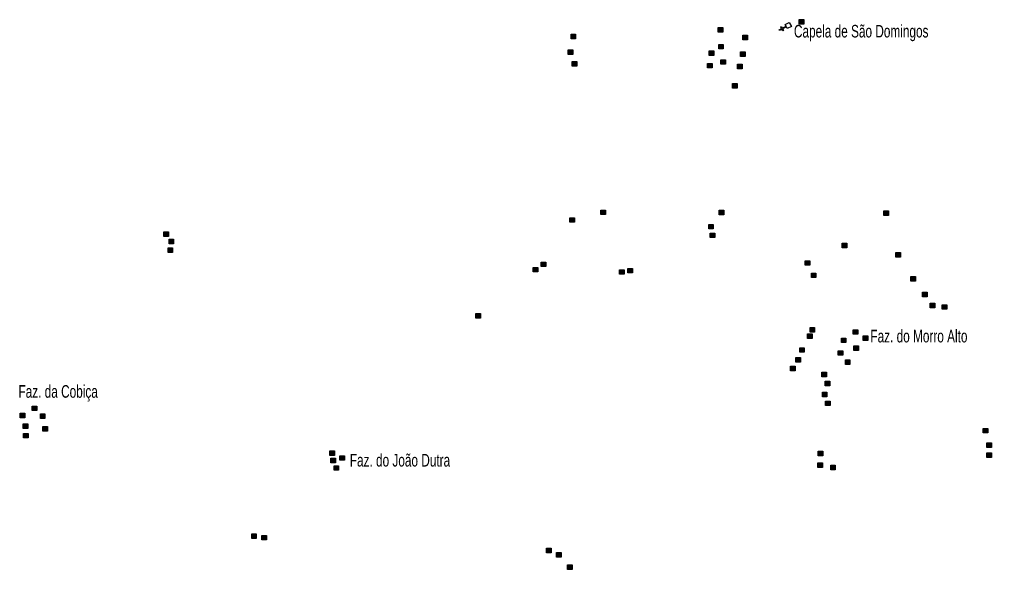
# Model space of a CAD drawing. Extents: x 265.7 to 292.1, y 7676.2 to 7704.2.
# Drawn here: x 273.19 to 279.36, y 7679.7 to 7683.19 of the extents above; entities that cross this region are included whole.
import ezdxf

# ---------------------------------------------------------------- set-up
doc = ezdxf.new("R2010")
doc.units = 0
doc.header["$LTSCALE"] = 0.032
doc.layers.add('2', color=7, linetype='Continuous', lineweight=25)
doc.layers.add('6', color=7, linetype='Continuous', lineweight=25)
doc.layers.add('61', color=7, linetype='Continuous')

msp = doc.modelspace()

# ---------------------------------------------------------------- hatches: boundary and pattern name
at = {"layer": '2'}
for points in [[(278.1366, 7683.192), (278.1656, 7683.192), (278.1656, 7683.163), (278.1366, 7683.163)], [(277.6228, 7683.1404), (277.6518, 7683.1404), (277.6518, 7683.1114), (277.6228, 7683.1114)], [(276.6889, 7683.0976), (276.7179, 7683.0976), (276.7179, 7683.0686), (276.6889, 7683.0686)], [(277.7786, 7683.0921), (277.8076, 7683.0921), (277.8076, 7683.0631), (277.7786, 7683.0631)], [(277.6259, 7683.0339), (277.6549, 7683.0339), (277.6549, 7683.0049), (277.6259, 7683.0049)], [(276.6712, 7682.9983), (276.7002, 7682.9983), (276.7002, 7682.9693), (276.6712, 7682.9693)], [(277.5647, 7682.9919), (277.5937, 7682.9919), (277.5937, 7682.9629), (277.5647, 7682.9629)], [(277.7649, 7682.9854), (277.7939, 7682.9854), (277.7939, 7682.9564), (277.7649, 7682.9564)], [(276.6955, 7682.925), (276.7245, 7682.925), (276.7245, 7682.896), (276.6955, 7682.896)], [(277.5549, 7682.9129), (277.5839, 7682.9129), (277.5839, 7682.8839), (277.5549, 7682.8839)], [(277.6397, 7682.9363), (277.6687, 7682.9363), (277.6687, 7682.9073), (277.6397, 7682.9073)], [(277.7455, 7682.9071), (277.7745, 7682.9071), (277.7745, 7682.8781), (277.7455, 7682.8781)], [(277.7139, 7682.7845), (277.7429, 7682.7845), (277.7429, 7682.7555), (277.7139, 7682.7555)], [(276.8787, 7681.9823), (276.9077, 7681.9823), (276.9077, 7681.9533), (276.8787, 7681.9533)], [(277.6284, 7681.9816), (277.6574, 7681.9816), (277.6574, 7681.9526), (277.6284, 7681.9526)], [(278.6744, 7681.9766), (278.7034, 7681.9766), (278.7034, 7681.9476), (278.6744, 7681.9476)], [(276.6817, 7681.9331), (276.7107, 7681.9331), (276.7107, 7681.9041), (276.6817, 7681.9041)], [(274.1056, 7681.8427), (274.1346, 7681.8427), (274.1346, 7681.8137), (274.1056, 7681.8137)], [(277.5622, 7681.8911), (277.5912, 7681.8911), (277.5912, 7681.8621), (277.5622, 7681.8621)], [(277.5719, 7681.8362), (277.6009, 7681.8362), (277.6009, 7681.8072), (277.5719, 7681.8072)], [(274.1379, 7681.7966), (274.1669, 7681.7966), (274.1669, 7681.7676), (274.1379, 7681.7676)], [(278.4088, 7681.7709), (278.4378, 7681.7709), (278.4378, 7681.7419), (278.4088, 7681.7419)], [(274.1314, 7681.7425), (274.1604, 7681.7425), (274.1604, 7681.7135), (274.1314, 7681.7135)], [(278.7502, 7681.712), (278.7792, 7681.712), (278.7792, 7681.683), (278.7502, 7681.683)], [(276.4993, 7681.6521), (276.5283, 7681.6521), (276.5283, 7681.6231), (276.4993, 7681.6231)], [(278.1739, 7681.6603), (278.2029, 7681.6603), (278.2029, 7681.6313), (278.1739, 7681.6313)], [(276.4493, 7681.6183), (276.4783, 7681.6183), (276.4783, 7681.5893), (276.4493, 7681.5893)], [(276.9964, 7681.603), (277.0254, 7681.603), (277.0254, 7681.574), (276.9964, 7681.574)], [(277.0498, 7681.6119), (277.0788, 7681.6119), (277.0788, 7681.5829), (277.0498, 7681.5829)], [(278.2136, 7681.5821), (278.2426, 7681.5821), (278.2426, 7681.5531), (278.2136, 7681.5531)], [(278.8454, 7681.5601), (278.8744, 7681.5601), (278.8744, 7681.5311), (278.8454, 7681.5311)], [(278.9197, 7681.4601), (278.9487, 7681.4601), (278.9487, 7681.4311), (278.9197, 7681.4311)], [(278.9681, 7681.39), (278.9971, 7681.39), (278.9971, 7681.361), (278.9681, 7681.361)], [(279.0439, 7681.381), (279.0729, 7681.381), (279.0729, 7681.352), (279.0439, 7681.352)], [(276.0846, 7681.3245), (276.1136, 7681.3245), (276.1136, 7681.2955), (276.0846, 7681.2955)], [(278.2054, 7681.2359), (278.2344, 7681.2359), (278.2344, 7681.2069), (278.2054, 7681.2069)], [(278.479, 7681.2221), (278.508, 7681.2221), (278.508, 7681.1931), (278.479, 7681.1931)], [(278.1892, 7681.1954), (278.2182, 7681.1954), (278.2182, 7681.1664), (278.1892, 7681.1664)], [(278.404, 7681.1696), (278.433, 7681.1696), (278.433, 7681.1406), (278.404, 7681.1406)], [(278.5428, 7681.1827), (278.5718, 7681.1827), (278.5718, 7681.1537), (278.5428, 7681.1537)], [(278.14, 7681.1082), (278.169, 7681.1082), (278.169, 7681.0792), (278.14, 7681.0792)], [(278.4831, 7681.1204), (278.5121, 7681.1204), (278.5121, 7681.0914), (278.4831, 7681.0914)], [(278.115, 7681.0461), (278.144, 7681.0461), (278.144, 7681.0171), (278.115, 7681.0171)], [(278.3845, 7681.0889), (278.4135, 7681.0889), (278.4135, 7681.0599), (278.3845, 7681.0599)], [(278.4297, 7681.0308), (278.4587, 7681.0308), (278.4587, 7681.0018), (278.4297, 7681.0018)], [(278.0812, 7680.9904), (278.1102, 7680.9904), (278.1102, 7680.9614), (278.0812, 7680.9614)], [(278.2798, 7680.9533), (278.3088, 7680.9533), (278.3088, 7680.9243), (278.2798, 7680.9243)], [(278.3022, 7680.8952), (278.3312, 7680.8952), (278.3312, 7680.8662), (278.3022, 7680.8662)], [(278.2838, 7680.8259), (278.3128, 7680.8259), (278.3128, 7680.7969), (278.2838, 7680.7969)], [(273.2695, 7680.7378), (273.2985, 7680.7378), (273.2985, 7680.7088), (273.2695, 7680.7088)], [(278.3031, 7680.7693), (278.3321, 7680.7693), (278.3321, 7680.7403), (278.3031, 7680.7403)], [(273.1928, 7680.6926), (273.2218, 7680.6926), (273.2218, 7680.6636), (273.1928, 7680.6636)], [(273.3212, 7680.6878), (273.3502, 7680.6878), (273.3502, 7680.6588), (273.3212, 7680.6588)], [(273.213, 7680.624), (273.242, 7680.624), (273.242, 7680.595), (273.213, 7680.595)], [(273.3373, 7680.6071), (273.3663, 7680.6071), (273.3663, 7680.5781), (273.3373, 7680.5781)], [(273.2147, 7680.5642), (273.2437, 7680.5642), (273.2437, 7680.5352), (273.2147, 7680.5352)], [(279.3038, 7680.5958), (279.3328, 7680.5958), (279.3328, 7680.5668), (279.3038, 7680.5668)], [(279.3273, 7680.5047), (279.3563, 7680.5047), (279.3563, 7680.4757), (279.3273, 7680.4757)], [(275.1587, 7680.4529), (275.1877, 7680.4529), (275.1877, 7680.4239), (275.1587, 7680.4239)], [(275.2218, 7680.4223), (275.2508, 7680.4223), (275.2508, 7680.3933), (275.2218, 7680.3933)], [(278.2572, 7680.4505), (278.2862, 7680.4505), (278.2862, 7680.4215), (278.2572, 7680.4215)], [(279.3281, 7680.4401), (279.3571, 7680.4401), (279.3571, 7680.4111), (279.3281, 7680.4111)], [(275.1653, 7680.4061), (275.1943, 7680.4061), (275.1943, 7680.3771), (275.1653, 7680.3771)], [(275.1846, 7680.3593), (275.2136, 7680.3593), (275.2136, 7680.3303), (275.1846, 7680.3303)], [(278.2555, 7680.377), (278.2845, 7680.377), (278.2845, 7680.348), (278.2555, 7680.348)], [(278.3362, 7680.3625), (278.3652, 7680.3625), (278.3652, 7680.3335), (278.3362, 7680.3335)], [(274.6625, 7679.9267), (274.6915, 7679.9267), (274.6915, 7679.8977), (274.6625, 7679.8977)], [(274.7271, 7679.917), (274.7561, 7679.917), (274.7561, 7679.888), (274.7271, 7679.888)], [(276.5332, 7679.8354), (276.5622, 7679.8354), (276.5622, 7679.8064), (276.5332, 7679.8064)], [(276.597, 7679.8073), (276.626, 7679.8073), (276.626, 7679.7783), (276.597, 7679.7783)], [(276.6672, 7679.7289), (276.6962, 7679.7289), (276.6962, 7679.6999), (276.6672, 7679.6999)]]:
    msp.add_hatch(color=256, dxfattribs=at).paths.add_polyline_path(points)

# ---------------------------------------------------------------- linework, layer by layer
for points in [[(278.1366, 7683.192), (278.1656, 7683.192), (278.1656, 7683.163), (278.1366, 7683.163)], [(277.6228, 7683.1404), (277.6518, 7683.1404), (277.6518, 7683.1114), (277.6228, 7683.1114)], [(276.6889, 7683.0976), (276.7179, 7683.0976), (276.7179, 7683.0686), (276.6889, 7683.0686)], [(277.7786, 7683.0921), (277.8076, 7683.0921), (277.8076, 7683.0631), (277.7786, 7683.0631)], [(277.6259, 7683.0339), (277.6549, 7683.0339), (277.6549, 7683.0049), (277.6259, 7683.0049)], [(276.6712, 7682.9983), (276.7002, 7682.9983), (276.7002, 7682.9693), (276.6712, 7682.9693)], [(277.5647, 7682.9919), (277.5937, 7682.9919), (277.5937, 7682.9629), (277.5647, 7682.9629)], [(277.7649, 7682.9854), (277.7939, 7682.9854), (277.7939, 7682.9564), (277.7649, 7682.9564)], [(276.6955, 7682.925), (276.7245, 7682.925), (276.7245, 7682.896), (276.6955, 7682.896)], [(277.5549, 7682.9129), (277.5839, 7682.9129), (277.5839, 7682.8839), (277.5549, 7682.8839)], [(277.6397, 7682.9363), (277.6687, 7682.9363), (277.6687, 7682.9073), (277.6397, 7682.9073)], [(277.7455, 7682.9071), (277.7745, 7682.9071), (277.7745, 7682.8781), (277.7455, 7682.8781)], [(277.7139, 7682.7845), (277.7429, 7682.7845), (277.7429, 7682.7555), (277.7139, 7682.7555)], [(276.8787, 7681.9823), (276.9077, 7681.9823), (276.9077, 7681.9533), (276.8787, 7681.9533)], [(277.6284, 7681.9816), (277.6574, 7681.9816), (277.6574, 7681.9526), (277.6284, 7681.9526)], [(278.6744, 7681.9766), (278.7034, 7681.9766), (278.7034, 7681.9476), (278.6744, 7681.9476)], [(276.6817, 7681.9331), (276.7107, 7681.9331), (276.7107, 7681.9041), (276.6817, 7681.9041)], [(274.1056, 7681.8427), (274.1346, 7681.8427), (274.1346, 7681.8137), (274.1056, 7681.8137)], [(277.5622, 7681.8911), (277.5912, 7681.8911), (277.5912, 7681.8621), (277.5622, 7681.8621)], [(277.5719, 7681.8362), (277.6009, 7681.8362), (277.6009, 7681.8072), (277.5719, 7681.8072)], [(274.1379, 7681.7966), (274.1669, 7681.7966), (274.1669, 7681.7676), (274.1379, 7681.7676)], [(278.4088, 7681.7709), (278.4378, 7681.7709), (278.4378, 7681.7419), (278.4088, 7681.7419)], [(274.1314, 7681.7425), (274.1604, 7681.7425), (274.1604, 7681.7135), (274.1314, 7681.7135)], [(278.7502, 7681.712), (278.7792, 7681.712), (278.7792, 7681.683), (278.7502, 7681.683)], [(276.4993, 7681.6521), (276.5283, 7681.6521), (276.5283, 7681.6231), (276.4993, 7681.6231)], [(278.1739, 7681.6603), (278.2029, 7681.6603), (278.2029, 7681.6313), (278.1739, 7681.6313)], [(276.4493, 7681.6183), (276.4783, 7681.6183), (276.4783, 7681.5893), (276.4493, 7681.5893)], [(276.9964, 7681.603), (277.0254, 7681.603), (277.0254, 7681.574), (276.9964, 7681.574)], [(277.0498, 7681.6119), (277.0788, 7681.6119), (277.0788, 7681.5829), (277.0498, 7681.5829)], [(278.2136, 7681.5821), (278.2426, 7681.5821), (278.2426, 7681.5531), (278.2136, 7681.5531)], [(278.8454, 7681.5601), (278.8744, 7681.5601), (278.8744, 7681.5311), (278.8454, 7681.5311)], [(278.9197, 7681.4601), (278.9487, 7681.4601), (278.9487, 7681.4311), (278.9197, 7681.4311)], [(278.9681, 7681.39), (278.9971, 7681.39), (278.9971, 7681.361), (278.9681, 7681.361)], [(279.0439, 7681.381), (279.0729, 7681.381), (279.0729, 7681.352), (279.0439, 7681.352)], [(276.0846, 7681.3245), (276.1136, 7681.3245), (276.1136, 7681.2955), (276.0846, 7681.2955)], [(278.2054, 7681.2359), (278.2344, 7681.2359), (278.2344, 7681.2069), (278.2054, 7681.2069)], [(278.479, 7681.2221), (278.508, 7681.2221), (278.508, 7681.1931), (278.479, 7681.1931)], [(278.1892, 7681.1954), (278.2182, 7681.1954), (278.2182, 7681.1664), (278.1892, 7681.1664)], [(278.404, 7681.1696), (278.433, 7681.1696), (278.433, 7681.1406), (278.404, 7681.1406)], [(278.5428, 7681.1827), (278.5718, 7681.1827), (278.5718, 7681.1537), (278.5428, 7681.1537)], [(278.14, 7681.1082), (278.169, 7681.1082), (278.169, 7681.0792), (278.14, 7681.0792)], [(278.4831, 7681.1204), (278.5121, 7681.1204), (278.5121, 7681.0914), (278.4831, 7681.0914)], [(278.115, 7681.0461), (278.144, 7681.0461), (278.144, 7681.0171), (278.115, 7681.0171)], [(278.3845, 7681.0889), (278.4135, 7681.0889), (278.4135, 7681.0599), (278.3845, 7681.0599)], [(278.4297, 7681.0308), (278.4587, 7681.0308), (278.4587, 7681.0018), (278.4297, 7681.0018)], [(278.0812, 7680.9904), (278.1102, 7680.9904), (278.1102, 7680.9614), (278.0812, 7680.9614)], [(278.2798, 7680.9533), (278.3088, 7680.9533), (278.3088, 7680.9243), (278.2798, 7680.9243)], [(278.3022, 7680.8952), (278.3312, 7680.8952), (278.3312, 7680.8662), (278.3022, 7680.8662)], [(278.2838, 7680.8259), (278.3128, 7680.8259), (278.3128, 7680.7969), (278.2838, 7680.7969)], [(273.2695, 7680.7378), (273.2985, 7680.7378), (273.2985, 7680.7088), (273.2695, 7680.7088)], [(278.3031, 7680.7693), (278.3321, 7680.7693), (278.3321, 7680.7403), (278.3031, 7680.7403)], [(273.1928, 7680.6926), (273.2218, 7680.6926), (273.2218, 7680.6636), (273.1928, 7680.6636)], [(273.3212, 7680.6878), (273.3502, 7680.6878), (273.3502, 7680.6588), (273.3212, 7680.6588)], [(273.213, 7680.624), (273.242, 7680.624), (273.242, 7680.595), (273.213, 7680.595)], [(273.3373, 7680.6071), (273.3663, 7680.6071), (273.3663, 7680.5781), (273.3373, 7680.5781)], [(273.2147, 7680.5642), (273.2437, 7680.5642), (273.2437, 7680.5352), (273.2147, 7680.5352)], [(279.3038, 7680.5958), (279.3328, 7680.5958), (279.3328, 7680.5668), (279.3038, 7680.5668)], [(279.3273, 7680.5047), (279.3563, 7680.5047), (279.3563, 7680.4757), (279.3273, 7680.4757)], [(275.1587, 7680.4529), (275.1877, 7680.4529), (275.1877, 7680.4239), (275.1587, 7680.4239)], [(275.2218, 7680.4223), (275.2508, 7680.4223), (275.2508, 7680.3933), (275.2218, 7680.3933)], [(278.2572, 7680.4505), (278.2862, 7680.4505), (278.2862, 7680.4215), (278.2572, 7680.4215)], [(279.3281, 7680.4401), (279.3571, 7680.4401), (279.3571, 7680.4111), (279.3281, 7680.4111)], [(275.1653, 7680.4061), (275.1943, 7680.4061), (275.1943, 7680.3771), (275.1653, 7680.3771)], [(275.1846, 7680.3593), (275.2136, 7680.3593), (275.2136, 7680.3303), (275.1846, 7680.3303)], [(278.2555, 7680.377), (278.2845, 7680.377), (278.2845, 7680.348), (278.2555, 7680.348)], [(278.3362, 7680.3625), (278.3652, 7680.3625), (278.3652, 7680.3335), (278.3362, 7680.3335)], [(274.6625, 7679.9267), (274.6915, 7679.9267), (274.6915, 7679.8977), (274.6625, 7679.8977)], [(274.7271, 7679.917), (274.7561, 7679.917), (274.7561, 7679.888), (274.7271, 7679.888)], [(276.5332, 7679.8354), (276.5622, 7679.8354), (276.5622, 7679.8064), (276.5332, 7679.8064)], [(276.597, 7679.8073), (276.626, 7679.8073), (276.626, 7679.7783), (276.597, 7679.7783)], [(276.6672, 7679.7289), (276.6962, 7679.7289), (276.6962, 7679.6999), (276.6672, 7679.6999)]]:
    msp.add_lwpolyline(points, close=True, dxfattribs=at)
at = {"layer": '6'}
for points in [[(278.0553, 7683.1451), (278.0313, 7683.1326), (278.0369, 7683.1218), (278.0325, 7683.1196), (278.0269, 7683.1303), (278.0124, 7683.1227), (278.0102, 7683.1269), (278.0247, 7683.1345), (278.0191, 7683.1453), (278.0234, 7683.1475), (278.029, 7683.1368), (278.053, 7683.1494)], [(278.053, 7683.1494), (278.0474, 7683.1601), (278.0731, 7683.1736), (278.0866, 7683.1479), (278.0609, 7683.1344), (278.0553, 7683.1451)]]:
    msp.add_lwpolyline(points, dxfattribs=at)

# ---------------------------------------------------------------- texts
at = {"layer": '61', "width": 0.7}
for s, p in [('Capela de São Domingos', (278.1033, 7683.0774)), ('Faz. do Morro Alto', (278.5883, 7681.1418)), ('Faz. da Cobiça', (273.1822, 7680.7906)), ('Faz. do João Dutra', (275.2846, 7680.3538))]:
    msp.add_text(s, height=0.08, dxfattribs=at).set_placement(p)

doc.saveas('drawing.dxf')
